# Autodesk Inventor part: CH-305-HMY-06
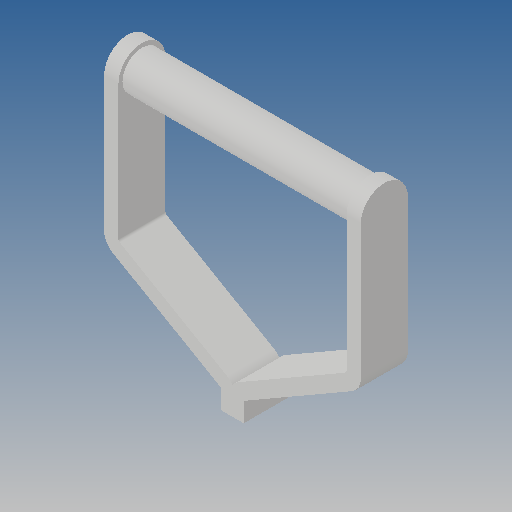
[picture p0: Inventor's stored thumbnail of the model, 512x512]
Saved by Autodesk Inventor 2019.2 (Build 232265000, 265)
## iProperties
Created: 2015-08
Part Number: CH-305-HMY-06
Material: Ogólny
Document SubType Name: Modeling
Designer: CADENGINEERING4
Density: 1 g/cm^3
Appearance: Domyślna
Author: CADENGINEERING4
Revision Number: ÈÎºÎ
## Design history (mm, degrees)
feature "NONE"
node "Bryła1"
